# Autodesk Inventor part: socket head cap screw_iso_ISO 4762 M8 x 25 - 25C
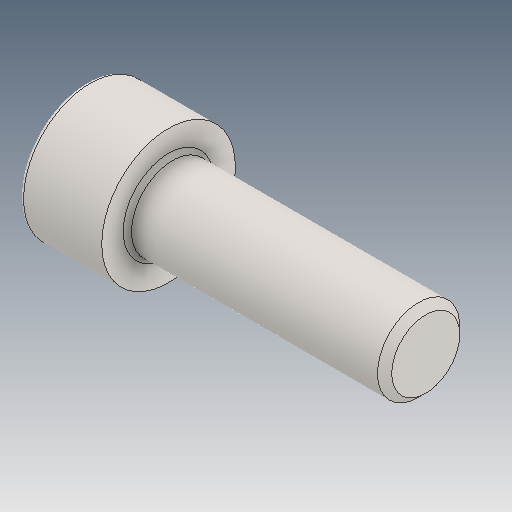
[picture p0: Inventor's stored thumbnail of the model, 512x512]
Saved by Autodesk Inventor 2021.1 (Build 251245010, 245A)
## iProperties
Created: 2021-05
Part Number: socket head cap screw_iso_ISO 4762 M8 x 25 - 25C
Material: Ogólny
Document SubType Name: Modeling
Designer: user
Density: 1 g/cm^3
Appearance: Domyślna
Author: user
Revision Number: ÈÎºÎ
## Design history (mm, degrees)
feature "ÊäÈë1"
node "Bryła1"
